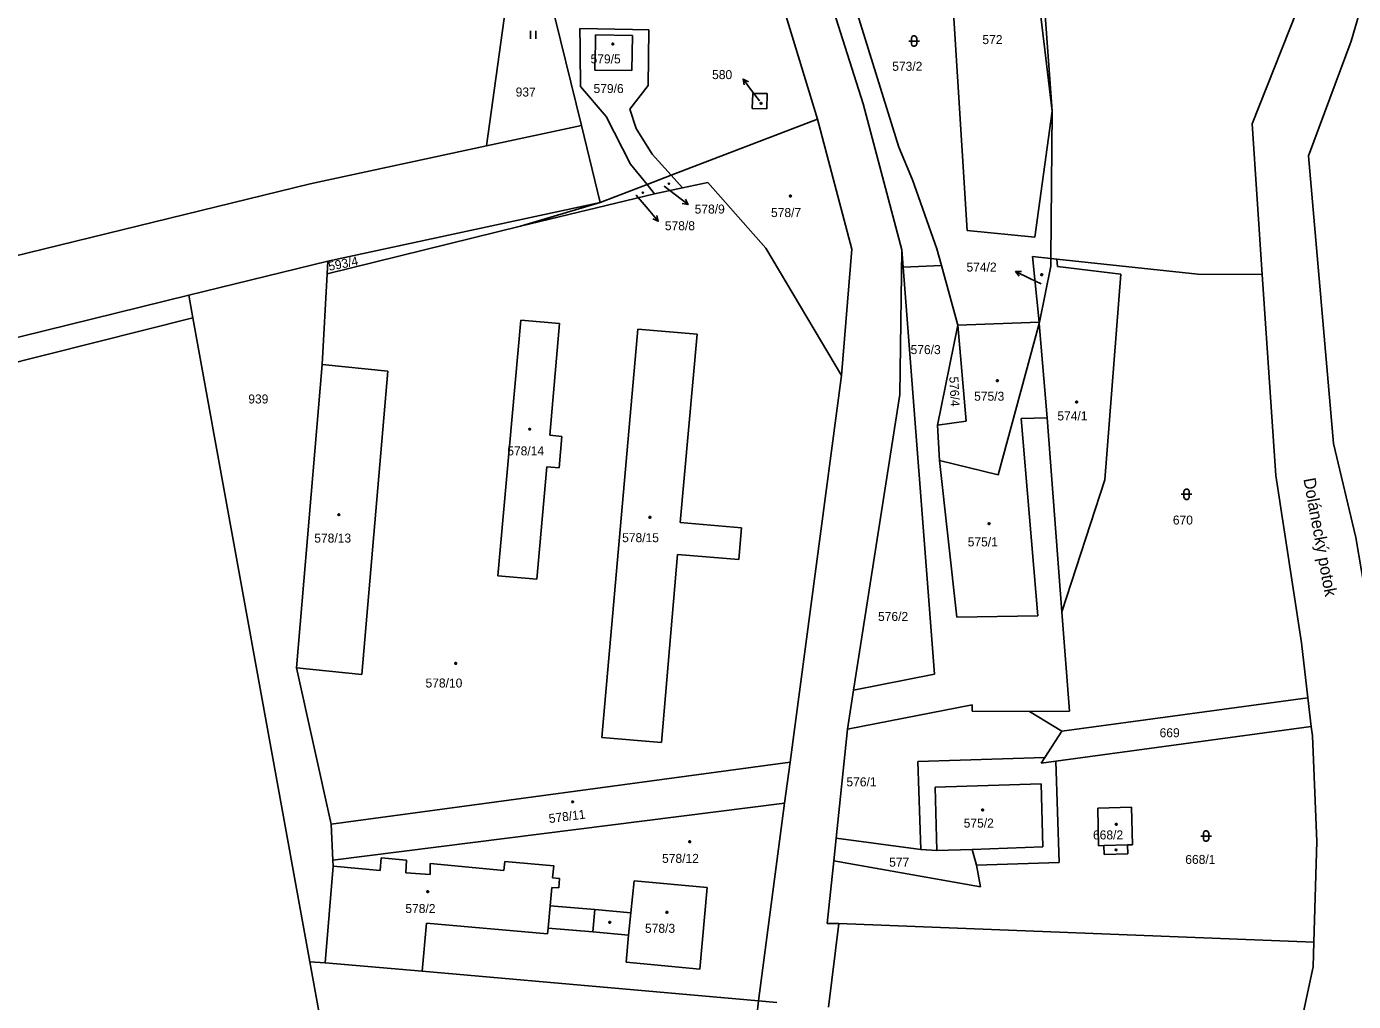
# Model space of a CAD drawing. Extents: x -812394 to -807601, y -1013097 to -1009266.
# Drawn here: x -809217.6 to -808967, y -1011991.8 to -1011807.5 of the extents above; entities that cross this region are included whole.
import ezdxf

# ---------------------------------------------------------------- set-up
doc = ezdxf.new("R2010")
doc.units = 0
for name, color, linetype in [('Default', 7, 'Continuous'), ('KN_HRANICE', 7, 'Continuous'), ('KN_KULTURY', 7, 'Continuous'), ('KN_PARCELY', 7, 'Continuous'), ('KN_SLUCKY', 7, 'Continuous')]:
    doc.layers.add(name, color=color, linetype=linetype)

# ---------------------------------------------------------------- blocks, each defined once
blk = doc.blocks.new('10292')
at = {"layer": 'Default'}
blk.add_line((0, 3), (0, 0), dxfattribs=at)
blk.add_lwpolyline([(-0.5, 2), (0, 3), (0.5, 2)], dxfattribs=at)
blk = doc.blocks.new('306')
at = {"layer": 'Default'}
for p, q in [((-0.5, 1.5), (-0.5, 0)), ((0.5, 0), (0.5, 1.5))]:
    blk.add_line(p, q, dxfattribs=at)
blk = doc.blocks.new('316')
at = {"layer": 'Default'}
for points in [[(-1, 1), (0.27, 1), (1, 1)], [(-0.5, 1.5), (-0.4, 1.79), (-0.15, 1.97), (0.16, 1.97), (0.41, 1.79), (0.51, 1.5), (0.51, 0.5), (0.41, 0.21), (0.16, 0.03), (-0.15, 0.03), (-0.4, 0.21), (-0.5, 0.5), (-0.5, 1.5)]]:
    blk.add_lwpolyline(points, dxfattribs=at)
blk = doc.blocks.new('NAHRADNI_SYMBOL')
at = {"layer": 'Default'}
blk.add_lwpolyline([(0.09, 0.15), (0.18, 0), (0.09, -0.15), (-0.09, -0.15), (-0.18, 0), (-0.09, 0.15), (0.09, 0.15)], dxfattribs=at)
blk = doc.blocks.new('402')
at = {"layer": 'Default'}
blk.add_lwpolyline([(0.09, 0.15), (0.18, 0), (0.09, -0.15), (-0.09, -0.15), (-0.18, 0), (-0.09, 0.15), (0.09, 0.15)], dxfattribs=at)

msp = doc.modelspace()

# ---------------------------------------------------------------- linework, layer by layer
at = {"layer": 'KN_HRANICE'}
for p, q in [((-809068.2, -1011824.99), (-809084.06, -1011773.13)), ((-809059.59, -1011822.15), (-809070.64, -1011787.15)), ((-809039.91, -1011846.09), (-809043.65, -1011786.86)), ((-809125.69, -1011793.95), (-809130.74, -1011830.07)), ((-809120.59, -1011794.42), (-809112.8, -1011826.22)), ((-809025.76, -1011797.55), (-809023.89, -1011823.5)), ((-809026.36, -1011802.99), (-809023.89, -1011823.5)), ((-809060.63, -1011805.19), (-809052.86, -1011830.28)), ((-808986.12, -1011825.88), (-808977.69, -1011804.62)), ((-809113.05, -1011811.37), (-809113.08, -1011807.88)), ((-809113.08, -1011807.88), (-809103.13, -1011808.08)), ((-809110.16, -1011811.48), (-809110.12, -1011809.06)), ((-809110.12, -1011809.06), (-809103.14, -1011809.22)), ((-809103.13, -1011808.08), (-809100.05, -1011808.14)), ((-809100.05, -1011808.14), (-809100.21, -1011818.65)), ((-809113.04, -1011812.38), (-809113.05, -1011811.37)), ((-809110.18, -1011812.48), (-809110.16, -1011811.48)), ((-809103.14, -1011809.22), (-809103.26, -1011815.85)), ((-809112.98, -1011818.85), (-809113.04, -1011812.38)), ((-809110.24, -1011815.74), (-809110.18, -1011812.48)), ((-809103.26, -1011815.85), (-809110.24, -1011815.74)), ((-809108.12, -1011824.53), (-809112.98, -1011818.85)), ((-809100.21, -1011818.65), (-809103.62, -1011823.1)), ((-809080.52, -1011823), (-809080.41, -1011820.15)), ((-809080.41, -1011820.15), (-809077.71, -1011820.19)), ((-809077.71, -1011820.19), (-809077.75, -1011823.05)), ((-809103.62, -1011823.1), (-809102.48, -1011826.76)), ((-809077.75, -1011823.05), (-809080.52, -1011823)), ((-809052.26, -1011849.71), (-809059.59, -1011822.15)), ((-809023.89, -1011823.5), (-809027.18, -1011847.34)), ((-809024.13, -1011851.34), (-809023.89, -1011823.5)), ((-809112.8, -1011826.22), (-809130.74, -1011830.07)), ((-809112.8, -1011826.22), (-809109.23, -1011840.79)), ((-809103.55, -1011833.5), (-809108.12, -1011824.53)), ((-809095.84, -1011835.63), (-809068.2, -1011824.99)), ((-809068.2, -1011824.99), (-809061.74, -1011849.58)), ((-808984.21, -1011854.38), (-808986.12, -1011825.88)), ((-809102.48, -1011826.76), (-809099.43, -1011831.65)), ((-809130.74, -1011830.07), (-809164.04, -1011837.22)), ((-809052.86, -1011830.28), (-809050.26, -1011836.49)), ((-809100.4, -1011837.39), (-809103.55, -1011833.5)), ((-809099.43, -1011831.65), (-809095.84, -1011835.63)), ((-809100.4, -1011837.39), (-809095.84, -1011835.63)), ((-809095.84, -1011835.63), (-809093.72, -1011837.98)), ((-809050.26, -1011836.49), (-809045.65, -1011849.55)), ((-809164.04, -1011837.22), (-809345.17, -1011881.72)), ((-809124.28, -1011845.23), (-809099, -1011839.11)), ((-809109.23, -1011840.79), (-809100.4, -1011837.39)), ((-809099, -1011839.11), (-809100.4, -1011837.39)), ((-809099, -1011839.11), (-809093.72, -1011837.98)), ((-809093.72, -1011837.98), (-809088.93, -1011836.97)), ((-809088.93, -1011836.97), (-809077.97, -1011849.39)), ((-809109.23, -1011840.79), (-809160.7, -1011851.85)), ((-809124.28, -1011845.23), (-809109.23, -1011840.79)), ((-809160.83, -1011854.23), (-809124.28, -1011845.23)), ((-809027.18, -1011847.34), (-809039.91, -1011846.09)), ((-809077.97, -1011849.39), (-809063.7, -1011873.44)), ((-809061.74, -1011849.58), (-809063.7, -1011873.44)), ((-809052.63, -1011877.06), (-809052.26, -1011849.71)), ((-809052.26, -1011849.71), (-809052.01, -1011852.97)), ((-809045.65, -1011849.55), (-809044.79, -1011852.69)), ((-809024.13, -1011851.34), (-809027.58, -1011850.96)), ((-809027.58, -1011850.96), (-809026.36, -1011863.36)), ((-809024.14, -1011852.83), (-809024.13, -1011851.34)), ((-809022.98, -1011851.46), (-809024.13, -1011851.34)), ((-808996.4, -1011854.34), (-809022.98, -1011851.46)), ((-809022.98, -1011851.46), (-809022.88, -1011852.88)), ((-809186.95, -1011858.3), (-809160.7, -1011851.85)), ((-809160.83, -1011854.23), (-809160.7, -1011851.85)), ((-809044.79, -1011852.69), (-809052.01, -1011852.97)), ((-809052.01, -1011852.97), (-809046.12, -1011929.91)), ((-809044.79, -1011852.69), (-809041.69, -1011863.94)), ((-809026.27, -1011863.41), (-809024.14, -1011852.83)), ((-809022.88, -1011852.88), (-809010.89, -1011854.29)), ((-809161.77, -1011871.36), (-809160.83, -1011854.23)), ((-809010.89, -1011854.29), (-809013.96, -1011893.21)), ((-808996.4, -1011854.34), (-808984.21, -1011854.38)), ((-808981.65, -1011892.37), (-808984.21, -1011854.38)), ((-809186.95, -1011858.3), (-809342.02, -1011896.39)), ((-809186.18, -1011862.56), (-809186.95, -1011858.3)), ((-809186.18, -1011862.56), (-809261.37, -1011881.55)), ((-809164.07, -1011984.25), (-809186.18, -1011862.56)), ((-809128.55, -1011911.3), (-809124.24, -1011862.99)), ((-809124.24, -1011862.99), (-809116.9, -1011863.65)), ((-809116.9, -1011863.65), (-809118.76, -1011884.76)), ((-809041.69, -1011863.94), (-809045.57, -1011882.86)), ((-809041.69, -1011863.94), (-809026.36, -1011863.36)), ((-809041.69, -1011863.94), (-809040.13, -1011882.07)), ((-809034.07, -1011892.23), (-809026.34, -1011863.65)), ((-809026.34, -1011863.65), (-809026.36, -1011863.36)), ((-809026.34, -1011863.65), (-809026.27, -1011863.41)), ((-809024.85, -1011881.48), (-809026.34, -1011863.65)), ((-809108.95, -1011941.85), (-809102.15, -1011864.7)), ((-809102.15, -1011864.7), (-809090.9, -1011865.67)), ((-809090.9, -1011865.67), (-809094.12, -1011901.22)), ((-809161.77, -1011871.36), (-809166.58, -1011928.68)), ((-809161.77, -1011871.36), (-809149.38, -1011872.63)), ((-809149.38, -1011872.63), (-809154.29, -1011929.97)), ((-809063.7, -1011873.44), (-809073.39, -1011946.52)), ((-809061.41, -1011932.96), (-809052.63, -1011877.06)), ((-809029.72, -1011881.59), (-809024.85, -1011881.48)), ((-809026.6, -1011918.86), (-809029.72, -1011881.59)), ((-809024.85, -1011881.48), (-809022.04, -1011918.12)), ((-809040.13, -1011882.07), (-809045.57, -1011882.86)), ((-809045.57, -1011882.86), (-809045.15, -1011889.54)), ((-809118.76, -1011884.76), (-809116.47, -1011884.97)), ((-809116.47, -1011884.97), (-809117, -1011890.94)), ((-809119.3, -1011890.74), (-809121.18, -1011911.95)), ((-809117, -1011890.94), (-809119.3, -1011890.74)), ((-809045.15, -1011889.54), (-809034.07, -1011892.23)), ((-809045.15, -1011889.54), (-809041.91, -1011919.15)), ((-809022.04, -1011918.12), (-809013.96, -1011893.21)), ((-808976.79, -1011923.99), (-808981.65, -1011892.37)), ((-809094.12, -1011901.22), (-809082.56, -1011902.24)), ((-809082.56, -1011902.24), (-809083.08, -1011908.25)), ((-809094.64, -1011907.27), (-809097.69, -1011942.84)), ((-809083.08, -1011908.25), (-809094.64, -1011907.27)), ((-809121.18, -1011911.95), (-809128.55, -1011911.3)), ((-809041.91, -1011919.15), (-809026.6, -1011918.86)), ((-809022.04, -1011918.12), (-809020.6, -1011936.88)), ((-808976.79, -1011923.99), (-808975.57, -1011934.41)), ((-809160.06, -1011958.27), (-809166.58, -1011928.68)), ((-809154.29, -1011929.97), (-809166.58, -1011928.68)), ((-809046.12, -1011929.91), (-809061.41, -1011932.96)), ((-809062.56, -1011940.27), (-809061.41, -1011932.96)), ((-809038.99, -1011935.72), (-809062.56, -1011940.27)), ((-809039.01, -1011936.88), (-809038.99, -1011935.72)), ((-809028.15, -1011936.97), (-809039.01, -1011936.88)), ((-809028.15, -1011936.97), (-809020.6, -1011936.88)), ((-809022.06, -1011940.69), (-808975.57, -1011934.41)), ((-808975.57, -1011934.41), (-808974.94, -1011939.81)), ((-809022.06, -1011940.69), (-809028.15, -1011936.97)), ((-809097.69, -1011942.84), (-809108.95, -1011941.85)), ((-809064.7, -1011960.93), (-809062.56, -1011940.27)), ((-809022.06, -1011940.69), (-809025.24, -1011945.65)), ((-809023.21, -1011946.38), (-808974.94, -1011939.81)), ((-808974.94, -1011939.81), (-808974.74, -1011941.54)), ((-808973.92, -1011961.54), (-808974.74, -1011941.54)), ((-809160.06, -1011958.27), (-809073.39, -1011946.52)), ((-809073.39, -1011946.52), (-809074.42, -1011954.31)), ((-809049.23, -1011946.44), (-809025.24, -1011945.65)), ((-809048.7, -1011963.03), (-809049.23, -1011946.44)), ((-809025.24, -1011945.65), (-809025.95, -1011946.75)), ((-809025.95, -1011946.75), (-809023.21, -1011946.38)), ((-809022.59, -1011965.49), (-809023.21, -1011946.38)), ((-809074.42, -1011954.31), (-809159.72, -1011965.09)), ((-809074.42, -1011954.31), (-809079.37, -1011991.64)), ((-809015.29, -1011955.26), (-809008.9, -1011955.07)), ((-809015.14, -1011962.32), (-809015.29, -1011955.26)), ((-809008.9, -1011955.07), (-809008.74, -1011962.13)), ((-809159.72, -1011965.09), (-809160.06, -1011958.27)), ((-809065.14, -1011965.21), (-809064.7, -1011960.93)), ((-809048.7, -1011963.03), (-809064.7, -1011960.93)), ((-808974.48, -1011980.56), (-808973.92, -1011961.54)), ((-809045.66, -1011963.24), (-809048.7, -1011963.03)), ((-809039.01, -1011963.02), (-809045.66, -1011963.24)), ((-809038.2, -1011965.99), (-809039.01, -1011963.02)), ((-809014.14, -1011962.29), (-809015.14, -1011962.32)), ((-809014.09, -1011963.99), (-809014.14, -1011962.29)), ((-809009.59, -1011963.86), (-809014.09, -1011963.99)), ((-809008.74, -1011962.13), (-809009.64, -1011962.15)), ((-809009.64, -1011962.15), (-809009.59, -1011963.86)), ((-809161.18, -1011984.49), (-809159.66, -1011966.19)), ((-809159.72, -1011965.09), (-809159.66, -1011966.19)), ((-809159.66, -1011966.19), (-809150.77, -1011967)), ((-809150.77, -1011967), (-809150.6, -1011964.6)), ((-809150.6, -1011964.6), (-809145.84, -1011965.06)), ((-809145.84, -1011965.06), (-809145.95, -1011967.43)), ((-809141.35, -1011967.76), (-809141.36, -1011965.71)), ((-809141.36, -1011965.71), (-809127.42, -1011967.04)), ((-809127.42, -1011967.04), (-809127.27, -1011965.28)), ((-809127.27, -1011965.28), (-809118.02, -1011966.1)), ((-809118.02, -1011966.1), (-809118.23, -1011968.41)), ((-809066.37, -1011977.01), (-809065.14, -1011965.21)), ((-809037.44, -1011970.1), (-809065.14, -1011965.21)), ((-809038.2, -1011965.99), (-809022.59, -1011965.49)), ((-809038.2, -1011965.99), (-809037.44, -1011970.1)), ((-809145.95, -1011967.43), (-809141.35, -1011967.76)), ((-809118.23, -1011968.41), (-809116.93, -1011968.53)), ((-809116.93, -1011968.53), (-809117.08, -1011970.31)), ((-809103.47, -1011974.99), (-809102.85, -1011968.95)), ((-809102.85, -1011968.95), (-809089.07, -1011970.21)), ((-809118.4, -1011970.2), (-809118.71, -1011973.66)), ((-809117.08, -1011970.31), (-809118.4, -1011970.2)), ((-809089.07, -1011970.21), (-809090.44, -1011985.64)), ((-809118.71, -1011973.66), (-809110.23, -1011974.41)), ((-809110.23, -1011974.41), (-809110.65, -1011978.63)), ((-809110.23, -1011974.41), (-809103.47, -1011974.99)), ((-809142.02, -1011976.94), (-809142.88, -1011986.01)), ((-809119.2, -1011978.96), (-809142.02, -1011976.94)), ((-809119.1, -1011977.88), (-809119.2, -1011978.96)), ((-809110.65, -1011978.63), (-809119.1, -1011977.88)), ((-809103.87, -1011979.23), (-809110.65, -1011978.63)), ((-809104.35, -1011984.34), (-809103.87, -1011979.23)), ((-809064.18, -1011977.03), (-809066.37, -1011977.01)), ((-809066.1, -1011992.82), (-809064.18, -1011977.03)), ((-809064.18, -1011977.03), (-808974.48, -1011980.56)), ((-809156.68, -1012024.93), (-809164.07, -1011984.25)), ((-809164.07, -1011984.25), (-809161.18, -1011984.49)), ((-809161.18, -1011984.49), (-809142.88, -1011986.01)), ((-809090.44, -1011985.64), (-809104.35, -1011984.34)), ((-809142.88, -1011986.01), (-809079.37, -1011991.64)), ((-809081.72, -1012014.75), (-809079.37, -1011991.64)), ((-809079.37, -1011991.64), (-809075.91, -1011991.94))]:
    msp.add_line(p, q, dxfattribs=at)
for points in [[(-808959.35, -1011971.59), (-808962.28, -1011929.28), (-808966.55, -1011904.05), (-808970.77, -1011886.31), (-808975.49, -1011831.97), (-808967.41, -1011810.26), (-808962, -1011791.72), (-808962.72, -1011776.44), (-808967.65, -1011744.41), (-808976.79, -1011718.1), (-808983.84, -1011699.49)], [(-808974.48, -1011980.56), (-808974.62, -1011985.2), (-808982.73, -1012023.07), (-808996.8, -1012054.74), (-809006.95, -1012078.24), (-809012.27, -1012096.04), (-809020.39, -1012144.75)]]:
    msp.add_lwpolyline(points, dxfattribs=at)
at = {"layer": 'KN_PARCELY'}
for p, q in [((-809079.16, -1011821.56), (-809080.45, -1011819.85)), ((-809097.16, -1011837.7), (-809095.02, -1011839.34)), ((-809102.48, -1011839.36), (-809100.21, -1011842.02)), ((-809025.95, -1011856.15), (-809028.1, -1011855.12))]:
    msp.add_line(p, q, dxfattribs=at)
at = {"layer": 'KN_SLUCKY'}
for p, q in [((-809045.95, -1011951.29), (-809025.99, -1011950.66)), ((-809045.66, -1011963.24), (-809045.95, -1011951.29)), ((-809025.99, -1011950.66), (-809025.67, -1011962.57)), ((-809025.67, -1011962.57), (-809039.01, -1011963.02)), ((-809014.14, -1011962.29), (-809009.64, -1011962.15)), ((-809118.71, -1011973.66), (-809119.1, -1011977.88)), ((-809103.47, -1011974.99), (-809103.87, -1011979.23))]:
    msp.add_line(p, q, dxfattribs=at)

# ---------------------------------------------------------------- block references
at = {"layer": 'KN_KULTURY'}
for name, p in [('306', (-809121.91, -1011809.83)), ('402', (-809106.86, -1011810.79)), ('316', (-809049.96, -1011811.27)), ('402', (-809078.87, -1011822.02)), ('NAHRADNI_SYMBOL', (-809073.31, -1011839.55)), ('NAHRADNI_SYMBOL', (-809025.85, -1011854.43)), ('NAHRADNI_SYMBOL', (-809034.22, -1011874.46)), ('NAHRADNI_SYMBOL', (-809019.27, -1011878.47)), ('402', (-809122.54, -1011883.61)), ('316', (-808998.5, -1011896.91)), ('402', (-809158.6, -1011899.76)), ('402', (-809099.86, -1011900.25)), ('402', (-809035.79, -1011901.47)), ('NAHRADNI_SYMBOL', (-809136.53, -1011927.88)), ('NAHRADNI_SYMBOL', (-809114.45, -1011954.04)), ('402', (-809037.02, -1011955.58)), ('402', (-809011.79, -1011958.29)), ('NAHRADNI_SYMBOL', (-809092.34, -1011961.57)), ('316', (-808994.81, -1011961.51)), ('402', (-809011.82, -1011963.1)), ('402', (-809141.81, -1011970.99)), ('402', (-809107.44, -1011976.81)), ('402', (-809096.65, -1011974.91))]:
    msp.add_blockref(name, p, dxfattribs=at)
at = {"layer": 'KN_KULTURY', "xscale": 0.67, "yscale": 0.67}
for p in [(-809101.19, -1011838.93), (-809096.26, -1011837.22)]:
    msp.add_blockref('NAHRADNI_SYMBOL', p, dxfattribs=at)
at = {"layer": 'KN_PARCELY'}
for p, rotation in [((-809080.45, -1011819.85), 37.013073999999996), ((-809095.02, -1011839.34), -127.43643100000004), ((-809100.21, -1011842.02), -139.64043199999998), ((-809028.1, -1011855.12), 64.400456)]:
    msp.add_blockref('10292', p, dxfattribs=dict(at, rotation=rotation))

# ---------------------------------------------------------------- texts
for s, height, p in [('572', 1.7, (-809037.06, -1011810.83)), ('579/5', 1.7, (-809111.06, -1011814.48)), ('573/2', 1.7, (-809054.09, -1011815.88)), ('580', 1.7, (-809088.11, -1011817.45)), ('937', 1.7, (-809125.21, -1011820.74)), ('579/6', 1.7, (-809110.5, -1011820.08)), ('580', 0.1, (-809079.3, -1011821.56)), ('578/9', 0.1, (-809097.4, -1011837.7)), ('578/8', 0.1, (-809102.72, -1011839.36)), ('578/9', 1.7, (-809091.4, -1011842.86)), ('578/7', 1.7, (-809076.98, -1011843.52)), ('578/8', 1.7, (-809097.03, -1011846.01)), ('574/2', 1.7, (-809040.06, -1011853.82)), ('576/3', 1.7, (-809050.62, -1011869.42)), ('575/3', 1.7, (-809038.62, -1011878.23)), ('939', 1.7, (-809175.7, -1011878.75)), ('574/1', 1.7, (-809022.9, -1011881.95)), ('578/14', 1.7, (-809126.79, -1011888.56)), ('670', 1.7, (-809001.09, -1011901.63)), ('578/13', 1.7, (-809163.24, -1011905.04)), ('578/15', 1.7, (-809105.1, -1011904.96)), ('575/1', 1.7, (-809039.83, -1011905.76)), ('576/2', 1.7, (-809056.77, -1011919.85)), ('578/10', 1.7, (-809142.23, -1011932.43)), ('669', 1.7, (-809003.59, -1011941.83)), ('576/1', 1.7, (-809062.74, -1011951.11)), ('575/2', 1.7, (-809040.59, -1011958.9)), ('668/2', 1.7, (-809016.17, -1011961.14)), ('578/12', 1.7, (-809097.56, -1011965.57)), ('668/1', 1.7, (-808998.74, -1011965.77)), ('577', 1.7, (-809054.67, -1011966.29)), ('578/2', 1.7, (-809146.04, -1011975.05)), ('578/3', 1.7, (-809100.78, -1011978.79))]:
    msp.add_text(s, height=height, dxfattribs=at).set_placement(p)
for s, height, rotation, p in [('593/4', 1.7, 11.23, (-809160.41, -1011853.7)), ('574/2', 0.1, 357.182, (-809025.97, -1011856.18)), ('576/4', 1.7, 272.785, (-809043.31, -1011873.68)), ('Dolánecký potok', 2.3, 280.463, (-808976.45, -1011893.02)), ('578/11', 1.7, 7.219, (-809118.84, -1011958.06))]:
    msp.add_text(s, height=height, rotation=rotation, dxfattribs=at).set_placement(p)

doc.saveas('drawing.dxf')
